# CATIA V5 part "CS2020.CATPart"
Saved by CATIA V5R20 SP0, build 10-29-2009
Part number: CS2020
Revision: 5
Definition: design
Nomenclature: CS2020
Source: made
Description: NOT SPECIFIED
Bounding box of the stored display mesh (mm): x -18.807 to 19, y -19 to 19, z -9 to 36
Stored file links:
  C:\Users\Raffaele\Desktop\3D X SITO CF\BOLEX\20-TILTED COLUMN SUPPORT\CS2020.CATPart
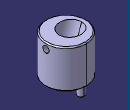
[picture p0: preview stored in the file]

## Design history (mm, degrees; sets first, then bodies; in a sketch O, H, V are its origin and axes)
Body1 "MANIFOLD_SOLID_BREP #695" (main body)
  Solid1: solid without history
